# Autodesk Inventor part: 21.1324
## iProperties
IsCustomPart: 1
Created: 2006-02
Part Number: 21.1324
Material: Steel, Mild
Description: M6X16 POINTED END DIN 914
Document SubType Name: Modeling
Standard: DIN 914
Designer: Andy Moles
Standards Organization: DIN
Language: en-US
Size Designation: M6 x 16
Categories: <MemberInstance><Categories><Category DisplayName="Fasteners" InternalName="e4da775c-781d-43d5-af7c-5136215cf5a6" Mnemonic="FSTN"><Category DisplayName="Bolts"
Density: 7.86 g/cm^3
Vendor: S
Mass: 3.0101 g
Surface Area: 3.5794 cm^2
Volume: 0.382964 cm^3
Author: Andy Moles
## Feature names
1. Body [Revolution]
2. Slot [Extrusion]
3. Chamfer1
4. Chamfer2
